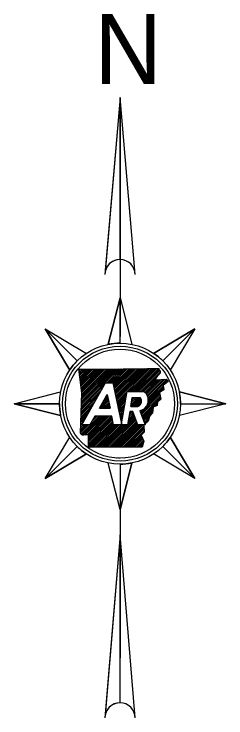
# Model space of a CAD drawing. Extents: x 21307 to 29830, y 1322443 to 1332359.
# Drawn here: x 26520.5 to 26658.8, y 1330674.7 to 1331134.4 of the extents above; entities that cross this region are included whole.
import ezdxf

# ---------------------------------------------------------------- set-up
doc = ezdxf.new("R2010")
doc.units = 0
doc.layers.add('R_Draft', color=7, linetype='Continuous')

msp = doc.modelspace()

# ---------------------------------------------------------------- linework, layer by layer
at = {"layer": 'R_Draft'}
for p, q in [((26589.69, 1331079.84), (26579.95, 1330965.91)), ((26589.69, 1331079.84), (26589.69, 1330923.82)), ((26589.69, 1330974.12), (26589.69, 1331079.84)), ((26580.14, 1330968.12), (26581.04, 1330969.02)), ((26580.08, 1330967.5), (26580.53, 1330967.95)), ((26589.69, 1330949.14), (26581.99, 1330918.74)), ((26589.69, 1330919.5), (26589.69, 1330949.14)), ((26540.78, 1330928.88), (26561.74, 1330907.93)), ((26561.74, 1330907.93), (26540.78, 1330928.88)), ((26540.78, 1330928.88), (26556.83, 1330901.95)), ((26638.59, 1330928.88), (26611.65, 1330912.83)), ((26617.63, 1330907.93), (26638.59, 1330928.88)), ((26617.63, 1330907.93), (26638.59, 1330928.88)), ((26562.75, 1330902.25), (26563.1, 1330902.6)), ((26562.87, 1330901.26), (26564.21, 1330902.6)), ((26563, 1330900.27), (26565.33, 1330902.6)), ((26563.12, 1330899.27), (26566.45, 1330902.6)), ((26563.24, 1330898.28), (26567.56, 1330902.6)), ((26563.37, 1330897.28), (26568.68, 1330902.6)), ((26563.49, 1330896.29), (26569.8, 1330902.6)), ((26563.61, 1330895.3), (26570.92, 1330902.6)), ((26563.74, 1330894.3), (26572.03, 1330902.6)), ((26563.86, 1330893.31), (26573.15, 1330902.6)), ((26563.99, 1330892.31), (26574.27, 1330902.6)), ((26564.11, 1330891.32), (26575.38, 1330902.6)), ((26564.23, 1330890.33), (26576.5, 1330902.59)), ((26564.36, 1330889.33), (26577.62, 1330902.59)), ((26564.39, 1330878.19), (26588.82, 1330902.62)), ((26564.43, 1330879.35), (26587.7, 1330902.61)), ((26564.47, 1330880.5), (26586.58, 1330902.61)), ((26564.48, 1330888.34), (26578.74, 1330902.6)), ((26564.51, 1330881.66), (26585.46, 1330902.61)), ((26564.55, 1330882.82), (26584.34, 1330902.61)), ((26564.59, 1330883.97), (26583.22, 1330902.6)), ((26564.6, 1330887.34), (26579.86, 1330902.6)), ((26564.62, 1330885.13), (26582.1, 1330902.6)), ((26564.66, 1330886.28), (26580.98, 1330902.6)), ((26580.99, 1330893.67), (26589.94, 1330902.62)), ((26582.11, 1330893.67), (26591.06, 1330902.62)), ((26583.23, 1330893.67), (26592.19, 1330902.63)), ((26584.35, 1330893.67), (26593.32, 1330902.65)), ((26585.04, 1330893.25), (26594.46, 1330902.67)), ((26585.24, 1330892.33), (26595.59, 1330902.68)), ((26585.44, 1330891.41), (26596.73, 1330902.7)), ((26585.63, 1330890.49), (26597.86, 1330902.72)), ((26585.83, 1330889.57), (26599, 1330902.74)), ((26586.03, 1330888.65), (26600.13, 1330902.75)), ((26586.23, 1330887.73), (26601.27, 1330902.77)), ((26586.42, 1330886.81), (26602.41, 1330902.79)), ((26586.62, 1330885.89), (26603.54, 1330902.81)), ((26586.82, 1330884.96), (26604.68, 1330902.82)), ((26587.01, 1330884.04), (26605.81, 1330902.84)), ((26587.21, 1330883.12), (26606.95, 1330902.86)), ((26587.41, 1330882.2), (26608.09, 1330902.88)), ((26587.6, 1330881.28), (26609.23, 1330902.91)), ((26595.37, 1330887.93), (26610.38, 1330902.93)), ((26596.49, 1330887.93), (26611.52, 1330902.96)), ((26597.61, 1330887.93), (26612.66, 1330902.99)), ((26598.72, 1330887.93), (26613.81, 1330903.01)), ((26599.84, 1330887.93), (26614.95, 1330903.04)), ((26600.96, 1330887.93), (26615.2, 1330902.17)), ((26602.08, 1330887.93), (26615.74, 1330901.59)), ((26603.19, 1330887.93), (26615.89, 1330900.62)), ((26604.31, 1330887.93), (26613.33, 1330896.95)), ((26605.33, 1330887.83), (26613.11, 1330895.61)), ((26605.94, 1330887.32), (26614.29, 1330895.67)), ((26606.48, 1330886.75), (26615.47, 1330895.73)), ((26606.97, 1330886.11), (26616.65, 1330895.79)), ((26607.38, 1330885.41), (26617.83, 1330895.86)), ((26607.72, 1330884.63), (26619.01, 1330895.92)), ((26607.98, 1330883.77), (26620.07, 1330895.86)), ((26608.13, 1330882.81), (26620.59, 1330895.26)), ((26620.09, 1330893.65), (26621.11, 1330894.67)), ((26564.36, 1330877.04), (26579.44, 1330892.12)), ((26564.73, 1330866.14), (26580.32, 1330893.67)), ((26580.32, 1330893.67), (26584.95, 1330893.67)), ((26607.9, 1330880.34), (26618.05, 1330890.49)), ((26608.14, 1330881.69), (26617.92, 1330891.48)), ((26564.28, 1330874.72), (26576.52, 1330886.96)), ((26564.32, 1330875.88), (26577.98, 1330889.54)), ((26576.2, 1330876.94), (26581.3, 1330885.95)), ((26587.8, 1330880.36), (26594.14, 1330886.7)), ((26594.36, 1330887.93), (26605.19, 1330887.93)), ((26603.29, 1330873.49), (26615.68, 1330885.88)), ((26606.93, 1330878.25), (26615.47, 1330886.79)), ((26616.8, 1330888.12), (26618.18, 1330889.5)), ((26658.85, 1330879.98), (26628.45, 1330887.68)), ((26564.2, 1330872.41), (26573.6, 1330881.81)), ((26564.24, 1330873.57), (26575.06, 1330884.39)), ((26576.25, 1330876.94), (26582, 1330882.69)), ((26577.37, 1330876.94), (26582.19, 1330881.77)), ((26577.59, 1330879.4), (26581.8, 1330883.61)), ((26579.04, 1330881.97), (26581.6, 1330884.53)), ((26580.5, 1330884.55), (26581.4, 1330885.45)), ((26588, 1330879.44), (26593.91, 1330885.35)), ((26588.2, 1330878.52), (26593.67, 1330884)), ((26588.39, 1330877.6), (26593.44, 1330882.64)), ((26588.59, 1330876.68), (26593.2, 1330881.29)), ((26596.72, 1330878.16), (26602.6, 1330884.04)), ((26596.94, 1330879.51), (26601.48, 1330884.04)), ((26597.18, 1330880.86), (26600.36, 1330884.04)), ((26597.42, 1330882.21), (26599.24, 1330884.04)), ((26597.65, 1330883.57), (26598.12, 1330884.04)), ((26597.73, 1330884.04), (26602.82, 1330884.04)), ((26597.83, 1330878.16), (26603.22, 1330883.55)), ((26598.95, 1330878.16), (26603.59, 1330882.81)), ((26600.07, 1330878.16), (26603.8, 1330881.89)), ((26603.59, 1330872.68), (26615.89, 1330884.98)), ((26603.89, 1330871.86), (26616.1, 1330884.07)), ((26604.19, 1330871.04), (26616.31, 1330883.16)), ((26520.52, 1330879.98), (26550.17, 1330879.98)), ((26550.17, 1330879.98), (26520.52, 1330879.98)), ((26520.52, 1330879.98), (26550.92, 1330872.28)), ((26564.13, 1330870.1), (26570.68, 1330876.66)), ((26564.16, 1330871.25), (26572.14, 1330879.23)), ((26576.2, 1330876.94), (26583.22, 1330876.94)), ((26578.49, 1330876.94), (26582.39, 1330880.85)), ((26579.6, 1330876.94), (26582.59, 1330879.93)), ((26580.72, 1330876.94), (26582.78, 1330879.01)), ((26581.84, 1330876.94), (26582.98, 1330878.08)), ((26582.96, 1330876.94), (26583.18, 1330877.16)), ((26588.79, 1330875.76), (26592.97, 1330879.94)), ((26588.98, 1330874.84), (26592.73, 1330878.58)), ((26589.18, 1330873.92), (26592.49, 1330877.23)), ((26596.71, 1330878.16), (26601.35, 1330878.16)), ((26601.19, 1330878.16), (26603.71, 1330880.68)), ((26602.99, 1330874.31), (26605.12, 1330876.44)), ((26604.5, 1330870.23), (26611.2, 1330876.93)), ((26612.49, 1330878.22), (26614.06, 1330879.79)), ((26629.21, 1330879.98), (26658.85, 1330879.98)), ((26629.21, 1330879.98), (26658.85, 1330879.98)), ((26564.09, 1330868.94), (26569.22, 1330874.08)), ((26564.25, 1330860.17), (26576, 1330871.91)), ((26564.92, 1330859.71), (26577.12, 1330871.91)), ((26565.72, 1330859.4), (26578.24, 1330871.91)), ((26567.05, 1330859.61), (26579.35, 1330871.91)), ((26568.18, 1330859.62), (26580.47, 1330871.91)), ((26569.06, 1330859.38), (26581.59, 1330871.91)), ((26569.1, 1330857.19), (26583.83, 1330871.91)), ((26569.1, 1330858.3), (26582.71, 1330871.91)), ((26573.35, 1330871.91), (26570.08, 1330866.14)), ((26571.34, 1330868.37), (26574.88, 1330871.91)), ((26572.8, 1330870.95), (26573.77, 1330871.91)), ((26584.3, 1330871.91), (26573.35, 1330871.91)), ((26589.38, 1330872.99), (26592.26, 1330875.87)), ((26589.58, 1330872.07), (26592.02, 1330874.52)), ((26589.77, 1330871.15), (26591.79, 1330873.17)), ((26589.97, 1330870.23), (26591.55, 1330871.81)), ((26595.04, 1330868.6), (26598.91, 1330872.47)), ((26595.28, 1330869.95), (26598.61, 1330873.28)), ((26595.51, 1330871.31), (26598.31, 1330874.1)), ((26595.75, 1330872.66), (26597.98, 1330874.89)), ((26595.99, 1330874.01), (26596.87, 1330874.89)), ((26598.02, 1330874.89), (26596.14, 1330874.89)), ((26601.25, 1330866.14), (26598.02, 1330874.89)), ((26602.6, 1330875.36), (26606.01, 1330866.14)), ((26602.69, 1330875.12), (26603.03, 1330875.46)), ((26604.8, 1330869.41), (26611.08, 1330875.69)), ((26605.1, 1330868.6), (26610.95, 1330874.45)), ((26564.01, 1330866.63), (26566.31, 1330868.93)), ((26564.05, 1330867.79), (26567.77, 1330871.5)), ((26569.1, 1330856.07), (26584.41, 1330871.38)), ((26569.1, 1330854.96), (26584.61, 1330870.46)), ((26569.11, 1330853.84), (26584.81, 1330869.54)), ((26569.11, 1330852.73), (26585.01, 1330868.62)), ((26569.13, 1330851.63), (26585.2, 1330867.7)), ((26580.29, 1330851.61), (26599.51, 1330870.84)), ((26581.4, 1330851.61), (26599.82, 1330870.02)), ((26582.52, 1330851.61), (26600.12, 1330869.2)), ((26583.64, 1330851.6), (26600.42, 1330868.39)), ((26584.75, 1330851.6), (26600.72, 1330867.57)), ((26590.17, 1330869.31), (26591.31, 1330870.46)), ((26590.36, 1330868.39), (26591.08, 1330869.11)), ((26590.56, 1330867.47), (26590.84, 1330867.75)), ((26594.81, 1330867.24), (26599.21, 1330871.65)), ((26605.4, 1330867.78), (26608.83, 1330871.21)), ((26605.7, 1330866.96), (26608.35, 1330869.61)), ((26563.84, 1330860.87), (26569.11, 1330866.14)), ((26563.86, 1330862.01), (26567.99, 1330866.14)), ((26563.9, 1330863.16), (26566.87, 1330866.14)), ((26563.93, 1330864.32), (26565.75, 1330866.14)), ((26563.97, 1330865.47), (26564.85, 1330866.35)), ((26570.08, 1330866.14), (26564.73, 1330866.14)), ((26570.25, 1330851.63), (26585.4, 1330866.78)), ((26571.36, 1330851.62), (26585.87, 1330866.14)), ((26572.48, 1330851.62), (26586.99, 1330866.14)), ((26573.59, 1330851.62), (26588.11, 1330866.14)), ((26574.71, 1330851.62), (26589.23, 1330866.14)), ((26575.82, 1330851.62), (26590.34, 1330866.14)), ((26576.94, 1330851.61), (26591.46, 1330866.14)), ((26578.06, 1330851.61), (26592.58, 1330866.14)), ((26579.17, 1330851.61), (26593.7, 1330866.14)), ((26594.61, 1330866.14), (26585.54, 1330866.14)), ((26585.87, 1330851.6), (26601.02, 1330866.75)), ((26586.98, 1330851.6), (26601.52, 1330866.14)), ((26588.1, 1330851.6), (26602.64, 1330866.14)), ((26589.22, 1330851.59), (26603.76, 1330866.14)), ((26590.33, 1330851.59), (26604.88, 1330866.14)), ((26591.45, 1330851.59), (26605.25, 1330865.39)), ((26592.56, 1330851.59), (26605.3, 1330864.32)), ((26593.68, 1330851.59), (26605.35, 1330863.26)), ((26606.01, 1330866.14), (26601.25, 1330866.14)), ((26594.8, 1330851.59), (26605.4, 1330862.19)), ((26595.91, 1330851.58), (26603.56, 1330859.23)), ((26597.03, 1330851.58), (26603.91, 1330858.46)), ((26638.59, 1330831.08), (26622.54, 1330858.01)), ((26598.14, 1330851.58), (26604.25, 1330857.69)), ((26599.26, 1330851.58), (26604.6, 1330856.92)), ((26600.38, 1330851.58), (26604.94, 1330856.14)), ((26601.49, 1330851.57), (26605.23, 1330855.31)), ((26602.61, 1330851.57), (26604.73, 1330853.69)), ((26540.78, 1330831.08), (26561.74, 1330852.03)), ((26561.74, 1330852.03), (26540.78, 1330831.08)), ((26603.72, 1330851.57), (26604.22, 1330852.07)), ((26617.63, 1330852.03), (26638.59, 1330831.08)), ((26617.63, 1330852.03), (26638.59, 1330831.08)), ((26540.78, 1330831.08), (26567.72, 1330847.13)), ((26589.68, 1330840.46), (26589.69, 1330840.46)), ((26589.69, 1330810.82), (26597.38, 1330841.22)), ((26589.69, 1330840.46), (26589.69, 1330713.94)), ((26589.69, 1330840.46), (26589.69, 1330810.82)), ((26589.69, 1330794.3), (26579.94, 1330676.37)), ((26589.69, 1330684.63), (26589.69, 1330794.3))]:
    msp.add_line(p, q, dxfattribs=at)
for points in [[(26599.57, 1330964.24), (26589.69, 1331079.84), (26579.81, 1330964.24)], [(26581.99, 1330918.74), (26589.69, 1330949.14), (26597.38, 1330918.74)], [(26556.83, 1330901.95), (26540.78, 1330928.88), (26567.72, 1330912.83)], [(26611.65, 1330912.83), (26638.59, 1330928.88), (26622.54, 1330901.95)], [(26562.7, 1330902.6), (26578.13, 1330902.59), (26591.66, 1330902.62), (26607.62, 1330902.87), (26615.02, 1330903.04)], [(26563.82, 1330860.88), (26564.68, 1330886.75), (26562.7, 1330902.6)], [(26619.87, 1330895.96), (26621.2, 1330894.56), (26617.88, 1330891.83), (26618.24, 1330889.07), (26615.38, 1330887.19), (26616.36, 1330882.94), (26614.16, 1330880.93), (26613.96, 1330878.75), (26611.29, 1330877.79), (26610.87, 1330873.67), (26608.95, 1330871.61), (26608.02, 1330868.51), (26605.22, 1330865.95), (26605.44, 1330861.43), (26603.53, 1330859.3), (26605.27, 1330855.42), (26604.07, 1330851.57)], [(26612.74, 1330895.59), (26619.97, 1330895.97)], [(26584.95, 1330893.67), (26590.69, 1330866.87), (26594.36, 1330887.93)], [(26550.92, 1330872.28), (26520.52, 1330879.98), (26550.92, 1330887.68)], [(26581.3, 1330885.95), (26583.22, 1330876.94)], [(26628.45, 1330887.68), (26658.85, 1330879.98), (26628.45, 1330872.28)], [(26596.71, 1330878.16), (26597.73, 1330884.04)], [(26585.54, 1330866.14), (26584.3, 1330871.91)], [(26596.14, 1330874.89), (26594.61, 1330866.14)], [(26567.72, 1330847.13), (26540.78, 1330831.08), (26556.83, 1330858.01)], [(26604.07, 1330851.57), (26569.11, 1330851.63), (26569.09, 1330859.34)], [(26622.54, 1330858.01), (26638.59, 1330831.08), (26611.65, 1330847.13)], [(26597.38, 1330841.22), (26589.69, 1330810.82), (26581.99, 1330841.22)], [(26599.57, 1330674.75), (26589.69, 1330794.3), (26579.81, 1330674.75)]]:
    msp.add_lwpolyline(points, dxfattribs=at)
for radius in [39.52, 37.54, 35.57]:
    msp.add_circle((26589.69, 1330879.98), radius, dxfattribs=at)
for centre, radius, start, end in [((26589.69, 1330964.24), 9.88, 0, 180), ((26589.69, 1330964.24), 9.88, 90, 170.2296), ((26589.69, 1330879.98), 39.52, 90, 101.2291), ((26589.69, 1330879.98), 39.52, 45, 56.2291), ((26589.69, 1330879.98), 39.52, 135, 146.2291), ((26601.16, 1330882.21), 7, 281.8626, 54.8705), ((26589.69, 1330879.98), 39.52, 0, 11.2291), ((26600.24, 1330881.56), 3.58, 288.1268, 43.8902), ((26589.69, 1330879.98), 39.52, 180, 191.2291), ((26589.69, 1330879.98), 39.52, 315, 326.2291), ((26589.69, 1330879.98), 39.52, 225, 236.2291), ((26589.69, 1330879.98), 39.52, 270, 281.2291), ((26589.69, 1330674.75), 9.88, 0, 180), ((26589.69, 1330674.75), 9.88, 90, 170.5511)]:
    msp.add_arc(centre, radius, start, end, dxfattribs=at)
for points in [[(26615.02, 1330903.04), (26615.07, 1330902.62), (26615.21, 1330902.4), (26615.22, 1330902), (26615.39, 1330901.83), (26615.66, 1330901.66), (26615.91, 1330901.38), (26615.97, 1330901.06), (26615.89, 1330900.72), (26615.87, 1330900.35), (26615.83, 1330900.03), (26615.78, 1330899.73), (26615.55, 1330899.49), (26615.33, 1330899.32), (26615.13, 1330899.12), (26614.99, 1330898.91), (26614.74, 1330898.68), (26614.49, 1330898.45), (26614.29, 1330898.24), (26614.09, 1330897.97), (26613.99, 1330897.67), (26613.77, 1330897.46), (26613.6, 1330897.27), (26613.37, 1330897.01), (26613.26, 1330896.76), (26613.04, 1330896.46), (26612.99, 1330896.18), (26612.85, 1330895.95), (26612.84, 1330895.91)], [(26569.09, 1330859.34), (26569.13, 1330859.32), (26568.95, 1330859.45), (26568.7, 1330859.57), (26568.43, 1330859.59), (26568.07, 1330859.64), (26567.78, 1330859.67), (26567.47, 1330859.87), (26567.15, 1330859.66), (26566.79, 1330859.51), (26566.58, 1330859.68), (26566.3, 1330859.56), (26566.11, 1330859.62), (26565.77, 1330859.39), (26565.46, 1330859.48), (26565.23, 1330859.41), (26564.95, 1330859.42), (26564.89, 1330859.74), (26564.61, 1330859.79), (26564.37, 1330859.92), (26564.21, 1330860.26), (26564.1, 1330860.52), (26563.82, 1330860.88)]]:
    msp.add_spline(points, degree=3, dxfattribs=at)

# ---------------------------------------------------------------- texts
for s, height, p in [('N', 45.6, (26573.02, 1331088.81)), ('DWB 7-27-17', 0.7685, (26587.27, 1330843.75))]:
    msp.add_text(s, height=height, dxfattribs=at).set_placement(p)

doc.saveas('drawing.dxf')
